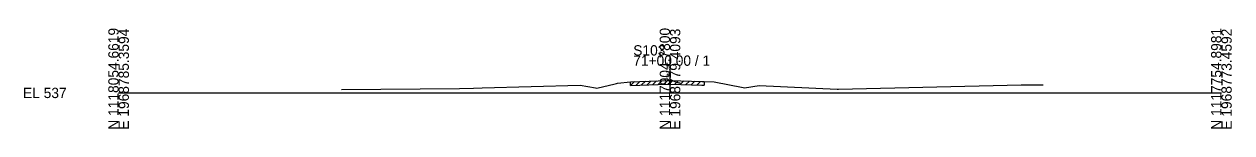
# Model space of a CAD drawing. Extents: x 974 to 1303, y 990 to 14518.
# Drawn here: x 974.3 to 1302.8, y 11990.3 to 12017.5 of the extents above; entities that cross this region are included whole.
import ezdxf

# ---------------------------------------------------------------- set-up
doc = ezdxf.new("R2010")
doc.units = 0
for name, color, linetype in [('Level 10', 7, 'Continuous'), ('Level 60', 7, 'Continuous'), ('Level 61', 7, 'Continuous'), ('Level 63', 7, 'Continuous')]:
    doc.layers.add(name, color=color, linetype=linetype)

msp = doc.modelspace()

# ---------------------------------------------------------------- linework, layer by layer
at = {"layer": 'Level 60'}
for p, q in [((1096.54, 12001.29), (1098.9, 12001.35)), ((1098.9, 12001.35), (1125.55, 12002.09)), ((1125.55, 12002.09), (1129.7, 12001.38)), ((1129.7, 12001.38), (1130.06, 12001.32)), ((1130.06, 12001.32), (1135.04, 12002.5)), ((1135.04, 12002.5), (1135.42, 12002.6)), ((1135.42, 12002.6), (1135.75, 12002.64)), ((1135.75, 12002.64), (1139.29, 12003.06)), ((1139.29, 12003.06), (1149.31, 12003.37)), ((1149.31, 12003.37), (1150.18, 12003.39)), ((1150.18, 12003.39), (1158.69, 12003.1)), ((1158.69, 12003.1), (1159.32, 12003.08)), ((1159.32, 12003.08), (1162.02, 12002.98)), ((1162.02, 12002.98), (1169.92, 12001.49)), ((1169.92, 12001.49), (1170.29, 12001.42)), ((1170.29, 12001.42), (1174.23, 12002.05)), ((1174.23, 12002.05), (1195.46, 12001.05)), ((1195.84, 12001.04), (1245.53, 12002.23)), ((1245.53, 12002.23), (1251.51, 12002.22)), ((1060.67, 12000.91), (1092.71, 12001.22)), ((1092.71, 12001.22), (1096.54, 12001.29)), ((1195.46, 12001.05), (1195.84, 12001.04))]:
    msp.add_line(p, q, dxfattribs=at)
at = {"layer": 'Level 61'}
for p, q in [((1139.29, 12002.06), (1140.32, 12003.1)), ((1139.29, 12002.06), (1139.29, 12003.06)), ((1139.29, 12002.06), (1149.31, 12002.37)), ((1140.79, 12002.11), (1141.82, 12003.14)), ((1142.29, 12002.16), (1143.32, 12003.19)), ((1143.79, 12002.2), (1144.82, 12003.23)), ((1145.29, 12002.25), (1146.32, 12003.28)), ((1146.79, 12002.29), (1147.82, 12003.32)), ((1148.29, 12002.34), (1149.32, 12003.37)), ((1149.31, 12002.37), (1150.18, 12002.39)), ((1149.79, 12002.38), (1150.78, 12003.37)), ((1150.18, 12002.39), (1158.69, 12002.1)), ((1151.29, 12002.36), (1152.26, 12003.32)), ((1152.79, 12002.3), (1153.76, 12003.27)), ((1154.29, 12002.25), (1155.26, 12003.22)), ((1155.79, 12002.2), (1156.76, 12003.17)), ((1157.29, 12002.15), (1158.26, 12003.12)), ((1158.69, 12002.1), (1159.32, 12002.08)), ((1159.32, 12003.08), (1159.32, 12002.08)), ((1159.32, 12002.08), (1159.32, 12002.08))]:
    msp.add_line(p, q, dxfattribs=at)
at = {"layer": 'Level 63'}
for p, q in [((1150, 12000), (1150, 12010.18)), ((1000, 12000), (1150, 12000)), ((1150, 12000), (1300, 12000))]:
    msp.add_line(p, q, dxfattribs=at)

# ---------------------------------------------------------------- texts
at = {"layer": 'Level 10'}
msp.add_text('540.39', height=0.9, rotation=90, dxfattribs=at).set_placement((1149.95, 12003.89))
at = {"layer": 'Level 63'}
for s, p in [('N 1118054.6619', (1000, 11990)), ('E 1968785.3594', (1002.8, 11990)), ('N 1117904.7800', (1150, 11990)), ('E 1968779.4093', (1152.8, 11990)), ('N 1117754.8981', (1300, 11990)), ('E 1968773.4592', (1302.8, 11990))]:
    msp.add_text(s, height=2.8, rotation=90, dxfattribs=at).set_placement(p)
for s, p in [('S103', (1140, 12010.18)), ('71+00.00 / 1', (1140, 12007.38)), ('EL 537', (974, 11998.6))]:
    msp.add_text(s, height=2.8, dxfattribs=at).set_placement(p)

doc.saveas('drawing.dxf')
